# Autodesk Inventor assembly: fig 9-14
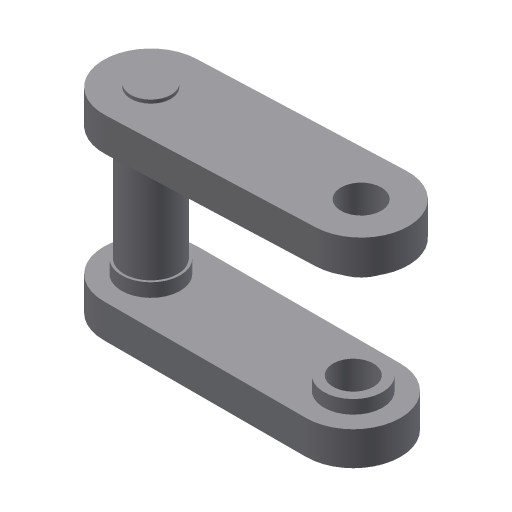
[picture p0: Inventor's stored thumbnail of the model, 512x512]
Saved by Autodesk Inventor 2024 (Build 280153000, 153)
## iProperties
Shininess: 64.0
Length Units: 11269
Angle Units: 11279
Time Units: 11290
Mass Units: 11283
Length Display Precision: 3
Angle Display Precision: 2
Created: 2002-01
Part Number: fig 9-14
Document SubType Name: Assembly
Designer: ***
Density: 0.0
Volumn: 0.0
Area: 0.0
PropertySet Name: Model Information
Control State: 0
Master: False
Checked Out: False
Author: ***
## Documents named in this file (3)
- D:\PROJECTS\Project 2023\RESOURCES INVENTOR 2024\RESOURCES INVENTOR 2024\Inventor_2023_Part\Inventor_2024_Part\c09_Inv_2024_prt\fig 9-14.iam
- D:\PROJECTS\Project 2023\RESOURCES INVENTOR 2024\RESOURCES INVENTOR 2024\Inventor_2023_Part\Inventor_2024_Part\c09_Inv_2024_prt\Part5.ipt
- D:\PROJECTS\Project 2023\RESOURCES INVENTOR 2024\RESOURCES INVENTOR 2024\Inventor_2023_Part\Inventor_2024_Part\c09_Inv_2024_prt\Part6.ipt
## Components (3 placed, 2 different names)
1. Part5:1 — Insert:1
2. Part6:1 — Insert:1, Insert:2
3. Part5:2 — Insert:2
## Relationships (2: Insert 2)
- Insert:1: Part5:1 ↔ Part6:1
- Insert:2: Part6:1 ↔ Part5:2
